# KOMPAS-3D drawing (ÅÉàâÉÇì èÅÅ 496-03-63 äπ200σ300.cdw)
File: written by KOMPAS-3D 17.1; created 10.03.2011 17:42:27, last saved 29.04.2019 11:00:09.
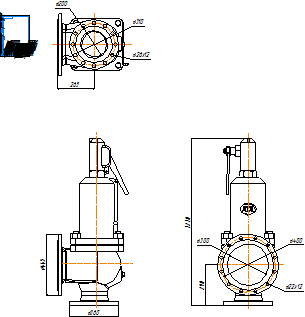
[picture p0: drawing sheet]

Sheet 1: A4, portrait

Title block, sheet 1: name: Прегран Ду200х300; material: Внимание! Данный продукт является объектом авторского права ООО «Торговый Дом АДЛ». / Запрещается изменение, копирование, распространение / (в том числе путем копирования на другие сайты и ресурсы в Интернете) / или любое иное использование информации и объектов без предварительного / согласия правообладателя (ООО «Торговый Дом АДЛ»).; scale: 1:1; sheets: 1; organisation: ООО "Торговый дом АДЛ"; sheet format: A4; stored path: C:\Users\tra\Desktop\2д чертежи\Предохранительные клапаны ПРЕГРАН\ПРЕГРАН 496\ПРЕГРАН КПП 496-03-63\KOMPAS 2D\Прегран Ду200х300.cdw

Views: Спереди 1, Проекционный вид 2, Проекционный вид 3
Dimensions and other numbers on the sheet: 360; 445; 400; 22; 300; 290; 1210; 310; 26; 200; 265; 1:1; 1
